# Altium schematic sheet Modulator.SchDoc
size A4; Organization: Altium Limited; Address1: L3, 12a Rodborough Rd; Address2: Frenchs Forest; Address3: NSW; Address4: Australia 2086
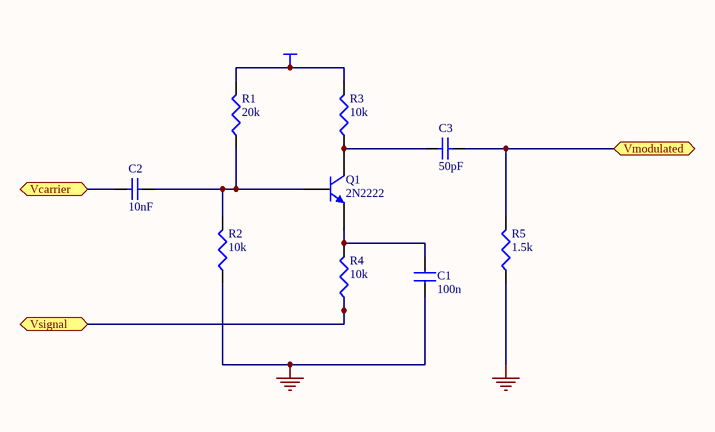
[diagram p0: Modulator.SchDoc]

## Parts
C1  100n
C2  10nF  [RAD-0.3]
C3  50pF  [RAD-0.3]
Q1  2N2222  [AXIAL-0.3]
R1  20k
R2  10k
R3  10k
R4  10k
R5  1.5k

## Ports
Vcarrier, Vmodulated, Vsignal

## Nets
GND: C1.1 R2.2(BOT) R5.2(BOT)
VCC: R1.1(TOP) R3.1(TOP)
Vcarrier: C2.1 ; port Vcarrier
Vmodulated: C3.2 R5.1(TOP) ; port Vmodulated
Vsignal: R4.2(BOT) ; port Vsignal
NetC1_2: C1.2 Q1.1(E) R4.1(TOP)
NetC2_2: C2.2 Q1.2(B) R1.2(BOT) R2.1(TOP)
NetC3_1: C3.1 Q1.3(C) R3.2(BOT)

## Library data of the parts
C1 = CAP: Capacitor
C2 C3 = Cap: Capacitor; Manufacturer: Generic Components; Class I: Passive
Q1 = 2N2222: General Purpose Transistor NPN Silicon; Manufacturer: Motorola; Package Information: Latest Revision: 1997; Class I: Discrete; Class II: BJT - Low Power
R1-R5 = RES: Resistor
